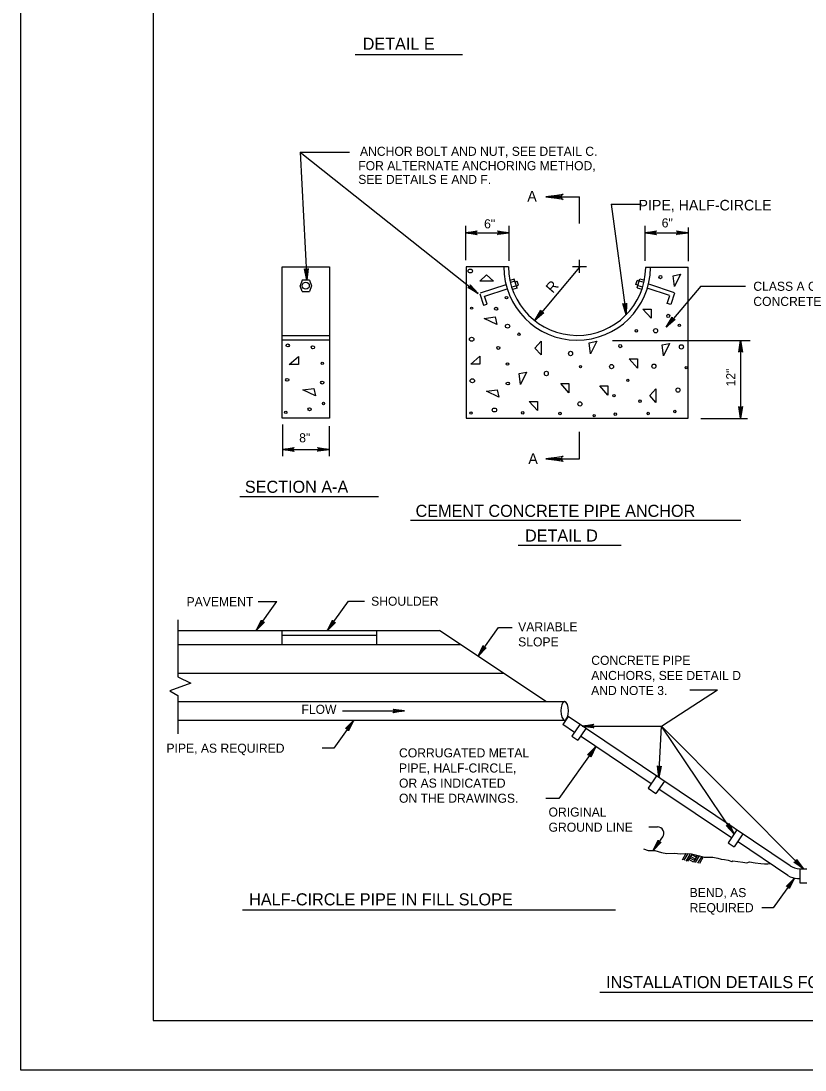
# Model space of a CAD drawing. Extents: x 5 to 910, y -47 to 547.
# Drawn here: x 4.7 to 241.8, y -46.5 to 270.9 of the extents above; entities that cross this region are included whole.
import ezdxf

# ---------------------------------------------------------------- set-up
doc = ezdxf.new("R2010")
doc.units = 0
for name, color, linetype in [('1', 7, 'Continuous'), ('2', 7, 'Continuous'), ('3', 7, 'Continuous'), ('PLT-BNDY', 7, 'Continuous')]:
    doc.layers.add(name, color=color, linetype=linetype)

msp = doc.modelspace()

# ---------------------------------------------------------------- linework, layer by layer
at = {"layer": '1'}
for p, q in [((205.74, 19.02), (204.65, 16.94)), ((206.32, 18.95), (205.2, 16.96)), ((207, 18.7), (205.81, 16.71)), ((207.53, 18.68), (206.29, 16.66)), ((206.57, 16.66), (206.41, 16.76)), ((208.08, 16.37), (206.64, 17.21)), ((208.49, 16.89), (206.87, 17.6)), ((208.76, 17.21), (207.21, 18.06)), ((209.02, 17.76), (207.51, 18.65)), ((209.2, 18.29), (208.08, 16.37)), ((209.77, 18.24), (208.58, 16.25)), ((209.2, 18.22), (208.92, 18.33)), ((210.46, 18.01), (209.29, 16.02)), ((210.96, 17.95), (209.91, 16))]:
    msp.add_line(p, q, dxfattribs=at)
msp.add_lwpolyline([(830.72, -31.53), (830.72, 532.47), (44.72, 532.47), (44.72, -31.53), (830.72, -31.53), (830.72, -5.17), (630.72, -5.17), (630.72, 59.51), (830.72, 59.51), (830.72, 88.47), (630.72, 88.47), (630.72, -31.53), (709.52, -31.53), (709.52, -5.17), (709.52, -31.53), (786.52, -31.53), (786.52, -5.17), (786.52, -17.48), (830.72, -17.48)], dxfattribs=at)
for points in [[(147.58, 192.19), (143.46, 192.19), (145.52, 194.07)], [(202.35, 190.55), (201.94, 193.84), (204.18, 194.32)], [(144.81, 180.94), (148.11, 181.35), (148.57, 179.11)], [(195.26, 183.75), (195.26, 181.01), (192.79, 183.75)], [(161.97, 173.99), (161.97, 169.87), (160.1, 171.93)], [(176.98, 170.23), (176.57, 173.53), (178.81, 174.01)], [(198.99, 169.57), (198.58, 172.89), (200.82, 173.34)], [(88.6, 166.96), (85.86, 166.96), (88.6, 169.43)], [(143.46, 167.05), (140.72, 167.05), (143.46, 169.52)], [(191.14, 168.68), (191.14, 165.91), (188.67, 168.68)], [(155.77, 160.94), (155.36, 164.24), (157.63, 164.69)], [(89.97, 159.34), (93.29, 159.75), (93.75, 157.49)], [(145.45, 158.88), (148.75, 159.3), (149.21, 157.06)], [(170.41, 161.17), (170.41, 158.4), (167.94, 161.17)], [(182.22, 160.49), (182.22, 157.72), (179.75, 160.49)], [(196.72, 159.62), (196.72, 155.47), (194.85, 157.56)], [(160.9, 155.8), (160.9, 153.05), (158.4, 155.8)]]:
    msp.add_lwpolyline(points, close=True, dxfattribs=at)
for centre, major_axis in [((140.57, 195.26), (-0.666, 0)), ((198.09, 193.41), (0, -0.499)), ((151.52, 187.16), (-0.381, 0)), ((140.99, 184.01), (-0.381, 0)), ((148.4, 183.85), (-0.499, 0)), ((200.43, 181.69), (0, -0.499)), ((151.85, 178.57), (-0.666, 0)), ((196.63, 177.18), (0, -0.666)), ((203.83, 178.83), (0, -0.381)), ((141, 174.61), (-0.666, 0)), ((155.31, 176.13), (0, -0.381)), ((190.81, 177.16), (0, -0.381)), ((85.39, 172.75), (-0.499, 0)), ((93.01, 172.17), (-0.499, 0)), ((149.06, 172), (-0.499, 0)), ((185.92, 172.54), (0, -0.499)), ((204.42, 172.3), (0, -0.666)), ((170.91, 170.29), (0, -0.666)), ((95.83, 167.34), (-0.381, 0)), ((151.84, 167.11), (-0.381, 0)), ((173.91, 166.32), (0, -0.381)), ((183.3, 166.33), (0, -0.666)), ((196.11, 166.45), (0, -0.666)), ((205.86, 166.02), (0, -0.381)), ((85.24, 162.33), (-0.499, 0)), ((95.8, 161.5), (-0.499, 0)), ((141.21, 162.03), (-0.666, 0)), ((163.58, 164.25), (0, -0.666)), ((188.22, 162.16), (0, -0.381)), ((151.91, 161.22), (-0.499, 0)), ((203.4, 159.24), (0, -0.666)), ((173.73, 155.05), (0, -0.666)), ((184.04, 157.56), (0, -0.381)), ((191.92, 155.89), (0, -0.381)), ((84.78, 152.51), (-0.381, 0)), ((91.97, 153.44), (-0.499, 0)), ((96.2, 155.16), (0, -0.381)), ((140.79, 152.28), (-0.381, 0)), ((147.89, 153.2), (-0.666, 0)), ((156.44, 152.34), (0, -0.381)), ((167.71, 152.14), (0, -0.381)), ((194.37, 152.14), (0, -0.381)), ((202.44, 152.75), (0, -0.381)), ((178.04, 151.49), (0, -0.381)), ((184.43, 151.93), (0, -0.381))]:
    msp.add_ellipse(centre, major_axis=major_axis, ratio=0.9, dxfattribs=at)
at = {"layer": '2'}
for p, q in [((138.24, 260.71), (105.73, 260.71)), ((89.17, 231.2), (91.19, 192.49)), ((89.17, 231.2), (142.94, 188.49)), ((89.17, 231.2), (104.07, 231.2)), ((163.39, 217.73), (173.57, 217.73)), ((173.57, 209.65), (173.57, 217.73)), ((183.16, 215.49), (187.71, 181.99)), ((183.16, 215.49), (192.33, 215.49)), ((139.14, 208.92), (139.14, 198.51)), ((139.14, 206.81), (152.29, 206.81)), ((152.29, 208.92), (152.29, 198.37)), ((193.36, 208.92), (193.36, 198.37)), ((193.36, 206.81), (206.43, 206.81)), ((206.43, 208.46), (206.43, 198.19)), ((173.62, 194.69), (173.62, 198.69)), ((83.7, 196.52), (98, 196.52)), ((83.7, 150.76), (83.7, 196.52)), ((98, 196.52), (98, 150.76)), ((139.3, 196.52), (139.3, 150.76)), ((152.18, 196.52), (139.3, 196.52)), ((173.62, 196.43), (160.14, 180.32)), ((175.72, 196.52), (171.47, 196.52)), ((206.47, 196.34), (193.61, 196.34)), ((206.47, 150.76), (206.47, 196.41)), ((89.7, 192.49), (89.13, 190.8)), ((89.7, 189.09), (89.13, 190.8)), ((91.99, 192.49), (89.7, 192.49)), ((91.99, 192.49), (92.54, 190.8)), ((92.54, 190.8), (92.01, 189.09)), ((151.36, 191.12), (143.55, 188.56)), ((153.9, 192.79), (152.59, 192.41)), ((154.09, 192.15), (152.75, 191.74)), ((154.51, 190.78), (153.13, 190.39)), ((154.73, 190.1), (153.9, 192.79)), ((154.17, 191.97), (154.8, 192.16)), ((154.53, 190.77), (155.15, 190.96)), ((155.15, 190.96), (154.8, 192.16)), ((190.67, 191.18), (191, 192.35)), ((191.29, 190.98), (190.67, 191.18)), ((191.64, 192.16), (191, 192.35)), ((191.05, 190.22), (191.89, 192.92)), ((191.28, 190.9), (192.66, 190.51)), ((191.7, 192.27), (193.07, 191.86)), ((191.89, 192.92), (193.27, 192.53)), ((194.46, 191.33), (202.26, 188.76)), ((210.27, 190.71), (199.84, 178.24)), ((210.27, 190.71), (223.79, 190.71)), ((89.7, 189.09), (92.01, 189.09)), ((143.44, 188.35), (144.58, 184.9)), ((145.68, 185.26), (144.9, 187.6)), ((145, 187.69), (151.7, 189.88)), ((154.73, 190.1), (153.36, 189.69)), ((191.05, 190.22), (192.43, 189.81)), ((200.82, 187.9), (194.12, 190.09)), ((200.13, 185.47), (200.91, 187.8)), ((202.38, 188.56), (201.23, 185.1)), ((144.58, 184.9), (145.68, 185.26)), ((201.23, 185.1), (200.13, 185.47)), ((83.7, 175.7), (98, 175.7)), ((98, 174.33), (83.7, 174.33)), ((183.57, 174.24), (225.19, 174.24)), ((222.33, 174.24), (222.33, 150.78)), ((98, 150.76), (83.7, 150.76)), ((139.3, 150.76), (206.47, 150.76)), ((210.31, 150.6), (224.45, 150.6)), ((83.82, 148.8), (83.82, 139.19)), ((97.93, 148.31), (97.93, 139.19)), ((173.62, 138.43), (173.62, 146.62)), ((83.8, 141.27), (97.93, 141.27)), ((163.44, 138.43), (173.62, 138.43)), ((112.85, 126.9), (70.92, 126.9)), ((222.39, 119.75), (122.53, 119.75)), ((186.18, 112.23), (155.06, 112.23)), ((75.86, 86.49), (82.13, 95.25)), ((76.46, 95.25), (82.13, 95.25)), ((97.3, 86.4), (103.71, 95.34)), ((103.71, 95.34), (108.62, 95.34)), ((52.14, 89.72), (52.14, 72.49)), ((52.14, 86.49), (131.32, 86.49)), ((83.71, 82.21), (83.71, 86.51)), ((112.31, 82.21), (112.31, 86.51)), ((163.42, 65.03), (131.32, 86.49)), ((142.92, 78.73), (149.14, 87.43)), ((149.14, 87.43), (153.28, 87.43)), ((83.71, 85.07), (112.31, 85.07)), ((52.14, 82.21), (83.71, 82.21)), ((83.71, 82.21), (137.73, 82.21)), ((52.14, 73.61), (150.58, 73.61)), ((52.14, 66.81), (52.14, 55.24)), ((198.4, 57.55), (215.37, 68.52)), ((206.96, 68.52), (215.37, 68.52)), ((52.14, 65.03), (169.09, 65.03)), ((101.94, 62.12), (120.73, 62.12)), ((170.15, 60.45), (168.52, 58.07)), ((237.27, 15.31), (170.15, 60.45)), ((52.14, 59.31), (169.39, 59.31)), ((105.35, 59.31), (99.29, 50.84)), ((172.14, 55.65), (168.52, 58.07)), ((173.76, 58.03), (171.31, 54.46)), ((174.45, 57.55), (198.4, 57.55)), ((197.58, 41.99), (198.4, 57.55)), ((220.36, 24.85), (198.4, 57.55)), ((241.3, 14.33), (198.4, 57.55)), ((171.31, 54.46), (173.1, 53.25)), ((175.52, 56.84), (173.1, 53.25)), ((195.27, 40.09), (173.9, 54.46)), ((99.29, 50.84), (95.79, 50.84)), ((178.56, 51.33), (167.31, 35.61)), ((196.91, 42.45), (194.37, 38.74)), ((194.37, 38.74), (196.71, 37.14)), ((199.27, 40.87), (196.71, 37.14)), ((219.61, 23.73), (197.62, 38.51)), ((167.31, 35.61), (163.45, 35.61)), ((194.57, 27.03), (197.21, 27.03)), ((221.23, 26.11), (218.58, 22.22)), ((195.84, 19.89), (198.77, 23.99)), ((218.58, 22.22), (220.34, 21.03)), ((222.99, 24.9), (220.34, 21.03)), ((236.63, 12.36), (221.42, 22.59)), ((240.18, 14.38), (242.33, 14.31)), ((240.2, 14.38), (240.2, 10.1)), ((238.62, 11.54), (232.21, 2.59)), ((239.54, 11.42), (240.18, 11.4)), ((240.2, 10.1), (242.33, 10.1)), ((184.51, 1.86), (71.72, 1.86)), ((232.21, 2.59), (228.71, 2.59)), ((330.91, -23.05), (179.8, -23.05))]:
    msp.add_line(p, q, dxfattribs=at)
for points in [[(52.14, 72.49), (56.1, 70.57), (49.76, 68.19), (52.14, 66.81)], [(193, 20.37), (194.33, 19.89), (196.43, 19.89), (198.45, 19.27), (200.05, 19.04), (202.24, 19.11), (204.23, 18.93), (205.81, 19.04), (207.51, 18.86), (209.86, 18.27), (211.33, 17.85), (213.25, 17.85), (213.93, 17.85), (215.42, 17.58), (216.47, 17.24), (217.48, 17.17), (218.58, 16.94), (219.7, 16.55), (219.97, 16.8), (222.97, 16.39), (224.16, 16.21), (225.05, 16.44), (226.7, 16.16), (228.44, 15.95), (229.58, 15.82), (230.61, 15.89), (231.21, 15.98)]]:
    msp.add_lwpolyline(points, dxfattribs=at)
for centre, radius, start, end in [((172.9, 196.52), 22.18, 179.8227, 359.4681), ((172.91, 196.52), 20.73, 179.8735, 359.4941), ((197.2, 25.11), 1.92, 324.4432, 90), ((240.35, 19.86), 5.49, 236.0808, 268.293), ((239.69, 16.92), 5.49, 236.0864, 268.297)]:
    msp.add_arc(centre, radius, start, end, dxfattribs=at)
for centre, major_axis, start_param, end_param in [((169.38, 62.15), (0, -2.94), 3.352555, 6.084645), ((168.86, 62.15), (0, 2.92), 3.308332, 6.128868)]:
    msp.add_ellipse(centre, major_axis=major_axis, ratio=0.489887, start_param=start_param, end_param=end_param, dxfattribs=at)
at = {"layer": '3'}
for points in [[(168.38, 217.11), (168.2, 217.45), (163.39, 217.73), (168.38, 217.11), (168.63, 216.88), (163.39, 217.73), (168.2, 217.96), (168.36, 218.32), (163.39, 217.73), (168.63, 218.55), (168.36, 218.32)], [(142.46, 206.4), (142.34, 206.63), (139.14, 206.81), (142.46, 206.4), (142.64, 206.24), (139.14, 206.81), (142.34, 206.97), (142.46, 207.2), (139.14, 206.81), (142.64, 207.37), (142.46, 207.2)], [(148.98, 207.23), (149.09, 207), (152.29, 206.81), (148.98, 207.23), (148.79, 207.39), (152.29, 206.81), (149.09, 206.66), (148.98, 206.43), (152.29, 206.81), (148.79, 206.27), (148.98, 206.43)], [(196.68, 206.4), (196.56, 206.63), (193.36, 206.81), (196.68, 206.4), (196.86, 206.24), (193.36, 206.81), (196.56, 206.97), (196.68, 207.2), (193.36, 206.81), (196.86, 207.37), (196.68, 207.2)], [(203.11, 207.23), (203.22, 207), (206.43, 206.81), (203.11, 207.23), (202.92, 207.39), (206.43, 206.81), (203.22, 206.66), (203.11, 206.43), (206.43, 206.81), (202.92, 206.27), (203.11, 206.43)], [(91.44, 195.83), (91.19, 195.69), (91.19, 192.49), (91.44, 195.83), (91.57, 196.02), (91.19, 192.49), (90.87, 195.67), (90.61, 195.79), (91.19, 192.49), (90.45, 195.95), (90.61, 195.79)], [(140.6, 190.89), (140.53, 190.62), (142.94, 188.49), (140.6, 190.89), (140.56, 191.1), (142.94, 188.49), (140.33, 190.37), (140.1, 190.25), (142.94, 188.49), (139.85, 190.23), (140.1, 190.25)], [(187.69, 185.33), (187.46, 185.19), (187.71, 181.99), (187.69, 185.33), (187.8, 185.54), (187.71, 181.99), (187.12, 185.15), (186.86, 185.22), (187.71, 181.99), (186.68, 185.38), (186.86, 185.22)], [(162.59, 182.61), (162.34, 182.66), (160.14, 180.32), (162.59, 182.61), (162.82, 182.63), (160.14, 180.32), (162.06, 182.88), (161.97, 183.11), (160.14, 180.32), (161.95, 183.37), (161.97, 183.11)], [(202.28, 180.53), (202.03, 180.57), (199.84, 178.24), (202.28, 180.53), (202.51, 180.55), (199.84, 178.24), (201.76, 180.8), (201.67, 181.03), (199.84, 178.24), (201.64, 181.28), (201.67, 181.03)], [(221.91, 170.92), (222.14, 171.03), (222.33, 174.24), (221.91, 170.92), (221.75, 170.74), (222.33, 174.24), (222.49, 171.03), (222.71, 170.92), (222.33, 174.24), (222.87, 170.74), (222.71, 170.92)], [(222.74, 154.1), (222.51, 153.99), (222.33, 150.78), (222.74, 154.1), (222.9, 154.28), (222.33, 150.78), (222.17, 153.99), (221.94, 154.1), (222.33, 150.78), (221.78, 154.28), (221.94, 154.1)], [(87.11, 140.85), (87, 141.09), (83.8, 141.27), (87.11, 140.85), (87.3, 140.69), (83.8, 141.27), (87, 141.43), (87.11, 141.66), (83.8, 141.27), (87.3, 141.82), (87.11, 141.66)], [(94.62, 141.68), (94.73, 141.45), (97.93, 141.27), (94.62, 141.68), (94.43, 141.84), (97.93, 141.27), (94.73, 141.11), (94.62, 140.88), (97.93, 141.27), (94.43, 140.72), (94.62, 140.88)], [(168.42, 137.81), (168.24, 138.16), (163.44, 138.43), (168.42, 137.81), (168.68, 137.59), (163.44, 138.43), (168.24, 138.66), (168.4, 139.03), (163.44, 138.43), (168.68, 139.25), (168.4, 139.03)], [(168.42, 137.81), (168.24, 138.16), (163.44, 138.43), (168.42, 137.81), (168.68, 137.59), (163.44, 138.43), (168.24, 138.66), (168.4, 139.03), (163.44, 138.43), (168.68, 139.25), (168.4, 139.03)], [(78.13, 88.96), (77.88, 88.98), (75.86, 86.49), (78.13, 88.96), (78.36, 89.01), (75.86, 86.49), (77.6, 89.19), (77.46, 89.42), (75.86, 86.49), (77.44, 89.65), (77.46, 89.42)], [(99.56, 88.87), (99.31, 88.89), (97.3, 86.4), (99.56, 88.87), (99.79, 88.91), (97.3, 86.4), (99.04, 89.1), (98.9, 89.33), (97.3, 86.4), (98.88, 89.56), (98.9, 89.33)], [(145.18, 81.2), (144.93, 81.23), (142.92, 78.73), (145.18, 81.2), (145.41, 81.25), (142.92, 78.73), (144.66, 81.43), (144.52, 81.66), (142.92, 78.73), (144.5, 81.89), (144.52, 81.66)], [(117.41, 62.54), (117.52, 62.31), (120.73, 62.12), (117.41, 62.54), (117.23, 62.7), (120.73, 62.12), (117.52, 61.96), (117.41, 61.73), (120.73, 62.12), (117.23, 61.57), (117.41, 61.73)], [(103.09, 56.84), (103.34, 56.82), (105.35, 59.31), (103.09, 56.84), (102.86, 56.79), (105.35, 59.31), (103.61, 56.61), (103.75, 56.38), (105.35, 59.31), (103.77, 56.15), (103.75, 56.38)], [(177.76, 57.14), (177.65, 57.36), (174.45, 57.55), (177.76, 57.14), (177.95, 56.98), (174.45, 57.55), (177.65, 57.71), (177.76, 57.94), (174.45, 57.55), (177.95, 58.1), (177.76, 57.94)], [(176.3, 48.85), (176.55, 48.83), (178.56, 51.33), (176.3, 48.85), (176.07, 48.81), (178.56, 51.33), (176.83, 48.63), (176.96, 48.4), (178.56, 51.33), (176.99, 48.17), (176.96, 48.4)], [(198.17, 45.29), (197.92, 45.17), (197.58, 41.99), (198.17, 45.29), (198.33, 45.45), (197.58, 41.99), (197.58, 45.19), (197.35, 45.33), (197.58, 41.99), (197.21, 45.51), (197.35, 45.33)], [(218.85, 27.85), (218.72, 27.6), (220.36, 24.85), (218.85, 27.85), (218.88, 28.08), (220.36, 24.85), (218.44, 27.42), (218.19, 27.39), (220.36, 24.85), (217.96, 27.44), (218.19, 27.39)], [(198.1, 22.36), (197.85, 22.38), (195.84, 19.89), (198.1, 22.36), (198.33, 22.41), (195.84, 19.89), (197.58, 22.59), (197.44, 22.82), (195.84, 19.89), (197.42, 23.05), (197.44, 22.82)], [(239.26, 16.98), (239.17, 16.73), (241.3, 14.33), (239.26, 16.98), (239.24, 17.21), (241.3, 14.33), (238.94, 16.48), (238.69, 16.41), (241.3, 14.33), (238.44, 16.41), (238.69, 16.41)], [(236.36, 9.07), (236.61, 9.05), (238.62, 11.54), (236.36, 9.07), (236.13, 9.02), (238.62, 11.54), (236.88, 8.84), (237.02, 8.61), (238.62, 11.54), (237.04, 8.38), (237.02, 8.61)]]:
    msp.add_lwpolyline(points, dxfattribs=at)
msp.add_circle((90.83, 190.81), 1.07, dxfattribs=at)
at = {"layer": 'PLT-BNDY'}
msp.add_lwpolyline([(4.72, 547.47), (845.72, 547.47), (845.72, -46.53), (4.72, -46.53)], close=True, dxfattribs=at)

# ---------------------------------------------------------------- texts
at = {"layer": '3'}
for s, height, p in [('DETAIL E', 3.66, (108.05, 262.21)), ('ANCHOR BOLT AND NUT, SEE DETAIL C.', 2.7454, (107.23, 230.11)), ('FOR ALTERNATE ANCHORING METHOD,', 2.7454, (106.7, 225.76)), ('SEE DETAILS E AND F.', 2.7454, (106.7, 221.61)), (' A', 3.203, (156.64, 216.29)), (' PIPE, HALF-CIRCLE', 3.203, (190.27, 213.59)), ('6"', 2.745, (144.76, 208.17)), ('6"', 2.745, (198.47, 208.45)), ('CLASS A CEMENT', 2.7454, (226.17, 189.27)), ('CONCRETE', 2.745, (226.17, 184.69)), ('8"', 2.745, (88.85, 143.42)), (' A', 3.203, (156.96, 136.88)), ('SECTION A-A', 3.6603, (72.42, 128.14)), ('CEMENT CONCRETE PIPE ANCHOR', 3.6603, (124.04, 120.86)), ('DETAIL D', 3.66, (157.13, 113.38)), ('PAVEMENT', 2.745, (54.79, 93.83)), ('SHOULDER', 2.745, (110.59, 93.97)), ('VARIABLE', 2.745, (155.06, 86.23)), ('SLOPE', 2.745, (155.06, 81.66)), ('FLOW', 2.745, (89.52, 61.25)), ('PIPE, AS REQUIRED', 2.7454, (48.71, 49.49)), ('CORRUGATED METAL', 2.7454, (119.03, 48.08)), ('PIPE, HALF-CIRCLE,', 2.7454, (119.03, 43.5)), ('OR AS INDICATED', 2.7454, (119.03, 38.92)), ('ON THE DRAWINGS.', 2.7454, (119.03, 34.35)), ('ORIGINAL', 2.745, (164.25, 30.16)), ('GROUND LINE', 2.7454, (164.25, 25.58)), ('HALF-CIRCLE PIPE IN FILL SLOPE', 3.6603, (73.71, 3.29)), ('BEND, AS', 2.745, (206.92, 5.8)), ('REQUIRED', 2.745, (206.9, 1.23)), ('INSTALLATION DETAILS FOR HALF-CIRCLE PIPE', 3.6603, (181.64, -21.74))]:
    msp.add_text(s, height=height, dxfattribs=at).set_placement(p)
for s, height, rotation, p in [('R', 3.2, 49, (165.52, 188.33)), ('12"', 2.745, 90, (220.72, 160.34)), ('CONCRETE PIPE', 2.7454, 359.99, (177.16, 76.08)), ('ANCHORS, SEE DETAIL D', 2.7454, 359.99, (177.16, 71.5)), ('AND NOTE 3.', 2.7454, 359.99, (177.13, 66.95))]:
    msp.add_text(s, height=height, rotation=rotation, dxfattribs=at).set_placement(p)

doc.saveas('drawing.dxf')
